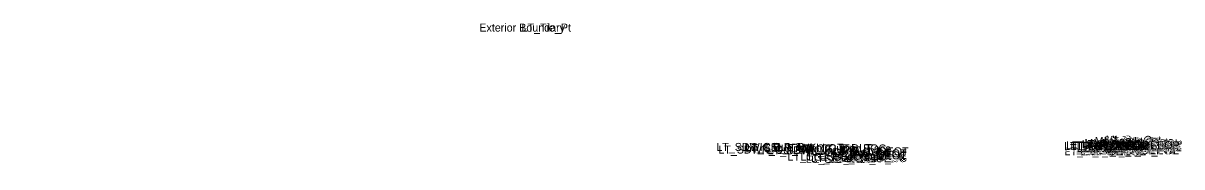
# Model space of a CAD drawing. Extents: x 0 to 6300, y 0 to 9528.
# Drawn here: x 3000 to 3144.7, y 2000 to 2018 of the extents above; entities that cross this region are included whole.
import ezdxf

# ---------------------------------------------------------------- set-up
doc = ezdxf.new("R2010")
doc.units = 0
doc.layers.add('Default', color=7, linetype='Continuous')

msp = doc.modelspace()

# ---------------------------------------------------------------- texts
at = {"layer": 'Default'}
for s, height, p in [('Exterior Boundary', 1, (3056.98, 2016.91)), ('LT_Tie_Pt', 1, (3062.26, 2016.91)), ('LT_PV2_OEEOP', 1, (3130.04, 2002.09)), ('LT_PV1_OEEOP', 1, (3130.27, 2002.21)), ('LT_PV2_IEEOP', 1, (3130.8, 2002.09)), ('LT_PV1_IEEOP', 1, (3131.04, 2002.21)), ('LT_PV2_PGL1', 1, (3131.63, 2002.09)), ('LT_PV2_PGL', 1, (3132.01, 2002.09)), ('LT_PV1_PGL', 1, (3132.25, 2002.34)), ('MI_Face In', 1, (3132.55, 2002.5)), ('MI_Bot In', 1, (3133.72, 2002.34)), ('MI_Top In', 1, (3133.84, 2002.75)), ('RT_PV2_OEEOP', 1, (3133.92, 2002.21)), ('RT_PV1_OEEOP', 1, (3134.16, 2002.33)), ('RT_PV2_IEEOP', 1, (3134.68, 2002.21)), ('RT_PV1_IEEOP', 1, (3134.92, 2002.33)), ('MI_Top Out', 1, (3135.1, 2002.87)), ('MI_Crown', 1, (3135.24, 2002.9)), ('MI_Face Out', 1, (3135.31, 2002.62)), ('RT_PV2_PGL1', 1, (3135.52, 2002.21)), ('RT_PV2_PGL', 1, (3135.9, 2002.21)), ('RT_PV1_PGL', 1, (3136.13, 2002.46)), ('MI_Bot Out', 1, (3136.5, 2002.46)), ('LT_SDWK_Out_Top', 1, (3086.58, 2001.99)), ('LT_SDWK_Out_Bot', 1, (3086.83, 2001.66)), ('LT_CSLP_Pnt', 1, (3090.1, 2001.99)), ('LT_Sub_Trench_Out_DLT', 1, (3090.21, 2001.84)), ('LT_SDWK_In_Top', 1, (3092.74, 2001.89)), ('LT_SDWK_In_Bot', 1, (3092.99, 2001.56)), ('LT_CG1_Shelf_Out', 1, (3095.48, 2000.77)), ('LT_CG_Top_BOC', 1, (3096.81, 2001.8)), ('LT_CG_Bot_BOC', 1, (3097.09, 2000.78)), ('LT_CG_Top_Face', 1, (3097.34, 2001.8)), ('LT_CG_Top_Gut', 1, (3097.87, 2001.3)), ('LT_Sub_OEOT_CG', 1, (3098.44, 2000.61)), ('LT_PV2_OEOT', 1, (3100.99, 2001.19)), ('LT_PV3_OEOT', 1, (3100.99, 2000.94)), ('LT_PV1_OEOT', 1, (3101.23, 2001.44)), ('LT_CG_Bot_IE', 1, (3101.34, 2000.86)), ('LT_PV3_OEEOP', 1, (3130.04, 2001.84)), ('LT_Sub_OEEOP', 1, (3130.08, 2001.46)), ('LT_PV3_PGL1', 1, (3131.63, 2001.84)), ('LT_PV4_PGL', 1, (3132.01, 2001.46)), ('RT_PV3_OEEOP', 1, (3133.92, 2001.96)), ('RT_Sub_OEEOP', 1, (3133.96, 2001.58)), ('RT_PV3_PGL1', 1, (3135.52, 2001.96)), ('RT_PV4_PGL', 1, (3135.9, 2001.58)), ('LT_Sub_OEOP', 1, (3097.77, 2000.51)), ('LT_Sub_OEOT', 1, (3101.04, 2000.57)), ('-', 0.0001, (3000, 2000))]:
    msp.add_text(s, height=height, dxfattribs=at).set_placement(p)

doc.saveas('drawing.dxf')
